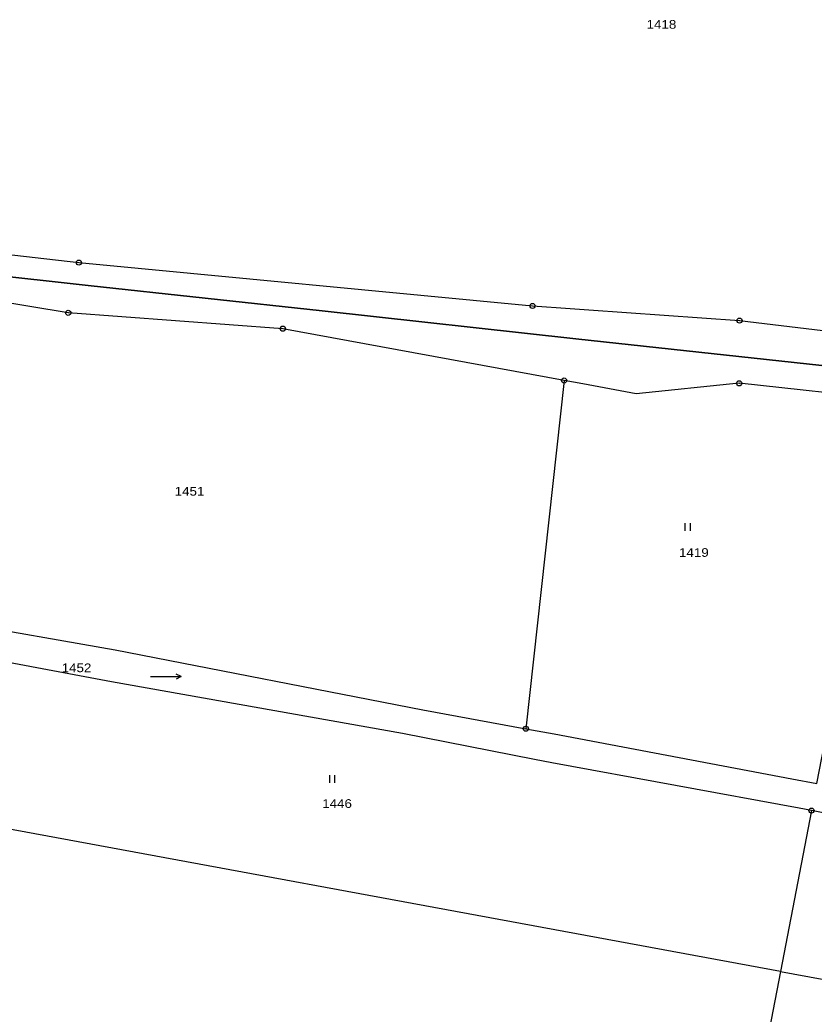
# Model space of a CAD drawing. Extents: x -872229 to -869198, y -1075981 to -1074329.
# Drawn here: x -870924.3 to -870769, y -1075586.7 to -1075392.2 of the extents above; entities that cross this region are included whole.
import ezdxf

# ---------------------------------------------------------------- set-up
doc = ezdxf.new("R2010")
doc.units = 0
doc.header["$LTSCALE"] = 0.68
for name, color, linetype, lineweight in [('1', 7, 'Continuous', 25), ('3', 7, 'Continuous', 25), ('6', 7, 'Continuous', 25), ('8', 7, 'Continuous', 25)]:
    doc.layers.add(name, color=color, linetype=linetype, lineweight=lineweight)
doc.layers.add('2', color=7, linetype='Continuous')

msp = doc.modelspace()

# ---------------------------------------------------------------- linework, layer by layer
at = {"layer": '1'}
msp.add_line((-870817.87, -1075462.75), (-870825.33, -1075530.87), dxfattribs=at)
for points in [[(-870949.31, -1075435.5), (-870912.76, -1075439.69), (-870824.05, -1075448.17), (-870816.69, -1075448.69), (-870813.04, -1075448.95), (-870783.54, -1075451.03), (-870689.55, -1075462.28), (-870596.02, -1075472.9), (-870575.95, -1075474.7)], [(-870817.87, -1075462.75), (-870872.87, -1075452.61), (-870914.84, -1075449.51), (-870944.51, -1075444.65)], [(-870753.84, -1075466.53), (-870783.62, -1075463.3), (-870803.76, -1075465.35), (-870814.2, -1075463.42), (-870817.87, -1075462.75)], [(-870825.33, -1075530.87), (-870819.8, -1075531.88), (-870773.33, -1075540.65), (-870768.45, -1075541.58), (-870753.84, -1075466.53)], [(-870955.2, -1075508.1), (-870936.99, -1075509.94), (-870905.68, -1075515.44), (-870845.51, -1075527.2), (-870825.33, -1075530.87)], [(-870769.48, -1075546.88), (-870771.86, -1075546.41), (-870820.28, -1075537.54), (-870823.66, -1075536.9), (-870849.48, -1075531.79), (-870906.42, -1075521.68), (-870938.07, -1075515.76), (-870962.39, -1075513.2), (-870967.23, -1075543.73)], [(-870775.56, -1075578.36), (-870961.39, -1075544.07), (-870967.23, -1075543.73)], [(-870769.48, -1075546.88), (-870775.56, -1075578.36), (-870723.44, -1075587.98), (-870658.76, -1075599.92), (-870633.02, -1075568.68)], [(-870633.02, -1075568.68), (-870643.23, -1075569.87), (-870653.67, -1075568.67), (-870711.88, -1075558.28), (-870769.48, -1075546.88)], [(-870775.56, -1075578.36), (-870796.43, -1075686.4), (-870817.54, -1075795.72)]]:
    msp.add_lwpolyline(points, dxfattribs=at)
at = {"layer": '3'}
for p, q in [((-870794.161, -1075492.14), (-870794.161, -1075490.64)), ((-870793.16, -1075492.14), (-870793.16, -1075490.64)), ((-870892.743, -1075520.669), (-870893.72, -1075521.17)), ((-870863.711, -1075541.45), (-870863.711, -1075539.95)), ((-870862.71, -1075541.45), (-870862.71, -1075539.95))]:
    msp.add_line(p, q, dxfattribs=at)
msp.add_lwpolyline([(-870898.743, -1075520.669), (-870892.743, -1075520.669), (-870893.72, -1075520.167)], dxfattribs=at)
at = {"layer": '6', "lineweight": 35}
msp.add_line((-870910.94, -1075444.16), (-870865.22, -1075449.1), dxfattribs=at)
for points in [[(-871015.95, -1075430.68), (-870979.48, -1075436.37), (-870951.66, -1075439.69), (-870910.94, -1075444.16)], [(-870865.22, -1075449.1), (-870815.6, -1075454.63), (-870759.62, -1075460.64)]]:
    msp.add_lwpolyline(points, dxfattribs=at)
at = {"layer": '8'}
for centre, radius in [((-870912.76, -1075439.6899), 0.5), ((-870912.76, -1075439.6899), 0.0303), ((-870824.05, -1075448.1699), 0.5), ((-870914.84, -1075449.5099), 0.5), ((-870914.84, -1075449.5099), 0.0303), ((-870824.05, -1075448.1699), 0.0303), ((-870783.54, -1075451.0299), 0.5), ((-870783.54, -1075451.0299), 0.0303), ((-870872.87, -1075452.6099), 0.5), ((-870872.87, -1075452.6099), 0.0303), ((-870817.87, -1075462.7499), 0.5), ((-870817.87, -1075462.7499), 0.0303), ((-870783.62, -1075463.2999), 0.5), ((-870783.62, -1075463.2999), 0.0303), ((-870825.33, -1075530.8699), 0.5), ((-870825.33, -1075530.8699), 0.0303), ((-870769.48, -1075546.8799), 0.5), ((-870769.48, -1075546.8799), 0.0303)]:
    msp.add_circle(centre, radius, dxfattribs=at)

# ---------------------------------------------------------------- texts
at = {"layer": '2', "width": 1.15}
for s, p in [('1418', (-870801.73, -1075393.93)), ('1451', (-870894.04, -1075485.27)), ('1419', (-870795.39, -1075497.25)), ('1452', (-870916.15, -1075519.81)), ('1446', (-870865.18, -1075546.36))]:
    msp.add_text(s, height=1.7, dxfattribs=at).set_placement(p)

doc.saveas('drawing.dxf')
